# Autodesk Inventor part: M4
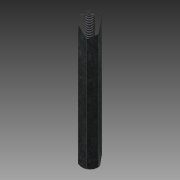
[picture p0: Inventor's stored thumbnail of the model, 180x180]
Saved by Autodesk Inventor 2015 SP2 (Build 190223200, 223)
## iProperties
Created: 2012-08
Part Number: M4
Material: Stahl
Document SubType Name: Modeling
Designer: rYan
Density: 7.85 g/cm^3
Mass: 3.36246 g
Surface Area: 5.74911 cm^2
Volume: 0.428339 cm^3
Appearance: Platte
Author: rYan
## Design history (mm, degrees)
derived "Abstandsbolzen Typ A.ipt"
feature "Volumenkörper1::Abstandsbolzen Typ A.ipt"
tag "Bezeichnung1"
node "Volumenkörper1"
other parameters: "SW" = 7, "d2" = 0, "d16" = 45 deg
